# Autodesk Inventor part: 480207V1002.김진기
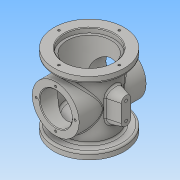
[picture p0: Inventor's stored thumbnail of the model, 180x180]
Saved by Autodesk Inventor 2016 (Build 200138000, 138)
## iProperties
Created: 2018-02
Part Number: 480207V1002.김진기
Material: 일반
Document SubType Name: Modeling
Designer: Administrator
Density: 1 g/cm^3
Appearance: 기본값
Author: Administrator
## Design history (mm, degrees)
sketch "스케치1"
  geometry: L1 (0, -54)-(0, 54); L2 (0, -54)-(-52.5, -54); L3 (-52.5, -54)-(-52.5, -44); L4 (-52.5, -44)-(-38, -44); L5 (-38, -44)-(-38, 44); L6 (-38, 44)-(-52.5, 44); L7 (-52.5, 44)-(-52.5, 54); L8 (-52.5, 54)-(0, 54); 2 further points
  constraints: 16 end point, 4 perpendicular, 2 point on line, 1 coincident, 1 horizontal, 1 midpoint, 1 parallel, 1 vertical, 1 vertical alignment
  dimensions: "d0" = 108 distance of L1.start L1.end; "d1" = 10 distance of L6.end L7.end; "d2" = 10 distance of L2.end L3.end; "d3" = 105 diameter of L7 L1; "d8" = 76 diameter of L5 L1
revolve "회전1" sketch "스케치1" stored, may be unused: angle "d5" = 90 deg
sketch "스케치3"
  geometry: L1 (-50, 0)-(50, 0); L2 (-50, 0)-(-50, 35); L3 (-50, 35)-(50, 35); L4 (50, 35)-(50, 0); 2 further points
  constraints: 8 end point, 2 perpendicular, 1 coincident, 1 horizontal, 1 midpoint, 1 vertical
  dimensions: "d9" = 100 distance of L1.start L1.end; "d10" = 70 diameter of L3 L1
revolve "회전2" sketch "스케치3" stored, may be unused: angle "d11" = 90 deg
sketch "스케치4"
  geometry: L1 (0, -32)-(0, 54); L2 (52.5, 54)-(-52.5, 54) reference; L3 (0, -32)-(-33, -32); L4 (-33, -32)-(-33, 47); L5 (-33, 47)-(-37, 47); L6 (-37, 47)-(-37, 54); L7 (-37, 54)-(0, 54); 1 further point
  constraints: 12 end point, 3 perpendicular, 2 point on line, 1 collinear, 1 horizontal, 1 midpoint, 1 vertical
  dimensions: "d22" = 74 diameter of L6 L1; "d23" = 66 diameter of L4 L1; "d24" = 7 distance between parallel lines of L2 L5; "d83" = 79 distance between parallel lines of L5 L3
revolve "회전3" sketch "스케치4" stored, may be unused: angle "d25" = 90 deg
hole "구멍2" diameter "d28" = 68; stored, may be unused: countersink angle "d32" = 90 deg, drill point angle "d34" = 0 deg; dims "d26" = 10, "d27" = 10, "d29" = 6, "d30" = 4, "d31" = 2, "d33" = 16
hole "구멍3" diameter "d37" = 10; stored, may be unused: countersink angle "d41" = 90 deg, drill point angle "d43" = 0 deg; dims "d35" = 10, "d36" = 10, "d38" = 6, "d39" = 4, "d40" = 2, "d42" = 16
hole "구멍4" diameter "d46" = 48; stored, may be unused: countersink angle "d50" = 90 deg, drill point angle "d52" = 0 deg; dims "d44" = 10, "d45" = 10, "d47" = 6, "d48" = 4, "d49" = 2, "d51" = 16
chamfer "모따기1" distance "d53" = 1; stored, may be unused: second distance "d54" = 2, angle "d55" = 45 deg
chamfer "모따기2" distance "d56" = 1; stored, may be unused: second distance "d57" = 2, angle "d58" = 45 deg
fillet "모깎기1" dims "d59" = 3
sketch "스케치5" dims "d32" = 90 deg
  geometry: 5 further points
  constraints: 2 horizontal alignment, 2 vertical alignment
  dimensions: "d60" = 45 distance of point (-45, 0) point (0, 0); "d61" = 45 distance of point (45, 0) point (0, 0); "d62" = 45 distance of point (0, 0) point (0, -45); "d63" = 45 distance of point (0, 45) point (0, 0)
hole "구멍5" sketch "스케치5" at (45, 0), (0, -45), (-45, 0), (0, 45) diameter "d64" = 3.242; stored, may be unused: countersink angle "d32" = 90 deg, countersink angle "d68" = 90 deg, drill point angle "d70" = 118 deg; dims "d65" = 4, "d66" = 4, "d67" = 2, "d69" = 6
fillet "모깎기2" dims "d71" = 3
sketch "스케치6"
  geometry: 5 further points
  constraints: 2 horizontal alignment, 2 vertical alignment
  dimensions: "d72" = 29 distance of point (-29, 0) point (0, 0); "d73" = 29 distance of point (29, 0) point (0, 0); "d74" = 29 distance of point (0, 29) point (0, 0); "d75" = 29 distance of point (0, -29) point (0, 0)
hole "구멍6" sketch "스케치6" at (0, 29), (29, 0), (0, -29), (-29, 0) diameter "d76" = 3.242; stored, may be unused: countersink angle "d80" = 90 deg, drill point angle "d82" = 118 deg; dims "d77" = 4, "d78" = 4, "d79" = 2, "d81" = 6
node "작업 평면2"
sketch "스케치7"
  geometry: L1 (-7, -13)-(-7, 13); L2 (7, -13)-(7, 13); A1 r 7 centre (0, 13) between (7, 13) and (-7, 13); A2 r 7 centre (0, -13) between (-7, -13) and (7, -13); 1 further point
  constraints: 4 end point, 4 point on circle, 3 tangent, 2 centre point, 2 vertical alignment, 1 parallel
  dimensions: "d85" = 7 radius of A1; "d86" = 7 radius of A2; "d88" = 13 distance of point (0, 0) A2.centre; "d89" = 13 distance of A1.centre point (0, 0)
extrude "돌출1" join sketch "스케치7" stored distance "d90" = 10; taper "d91" = 15 deg
fillet "모깎기3" dims "d92" = 3
hole "구멍7" diameter "d95" = 4.134; stored, may be unused: countersink angle "d99" = 90 deg, drill point angle "d101" = 118 deg; dims "d93" = 10, "d94" = 10, "d96" = 6, "d97" = 4, "d98" = 2, "d100" = 8
hole "구멍8" diameter "d104" = 4.134; stored, may be unused: countersink angle "d108" = 90 deg, drill point angle "d110" = 118 deg; dims "d102" = 10, "d103" = 10, "d105" = 6, "d106" = 4, "d107" = 2, "d109" = 8
node "솔리드1"
mirror "대칭1"
other parameters: "d84" = 55
